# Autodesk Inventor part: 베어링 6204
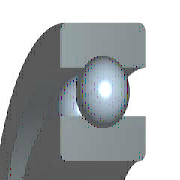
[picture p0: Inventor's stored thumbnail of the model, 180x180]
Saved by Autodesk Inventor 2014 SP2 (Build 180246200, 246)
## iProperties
IsCustomPart: 0
Created: 2009-02
Part Number: 베어링 6204
Material: 강, 연강
Description: 깊은 그루브 볼 베어링
Document SubType Name: Modeling
Standard: KS B 2023
Designer: KYOUNG IL JANG
Standards Organization: KS
Language: ko-KR
Size Designation: 6204 - 20 x 47 x 14
Categories: <MemberInstance><Categories><Category DisplayName="샤프트 부품" InternalName="7f7aeb1f-a693-4053-b835-cee3144e0d98" Mnemonic="SHFT"><Category DisplayName="베어링" Inter
Density: 7.86 g/cm^3
Mass: 104.255 g
Surface Area: 87.8912 cm^2
Volume: 13.264 cm^3
Appearance: 강철
Author: KYOUNG IL JANG
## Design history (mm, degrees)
sketch "스케치" dims "d0" = 7.02 (= -0.26 x WD + 0.26 x BD)
  geometry: L1 (3.49, 16.75)-(10.51, 16.75); L2 (7, 16.75)-(7, 13.24); L3 (7, 16.75)-(7, 20.26); L4 (4.392, 14.401)-(0, 14.401); L5 (0, 10)-(14, 10); L6 (4.392, 19.099)-(0, 19.099); L7 (0, 23.5)-(14, 23.5); L8 (14, 10)-(14, 14.401); L9 (9.608, 14.401)-(14, 14.401); L10 (9.608, 19.099)-(14, 19.099); L11 (14, 23.5)-(14, 19.099); L12 (-1.4, 0)-(8.4, 0) reference; L13 (0, -0.3)-(0, 5.3) reference
  constraints: 22 end point, 4 point on line, 2 collinear, 2 perpendicular, 2 symmetric about line, 1 midpoint, 1 parallel, 14 other
  dimensions: "d9" = 20 diameter of L5 L12 (= WD); "d11" = 47 diameter of L7 L12 (= BD); "d12" = 14 distance between parallel lines of L8 L13 (= KB); "d13" = 28.802 diameter of L9 L12 (= 0.326 x BD + 0.674 x WD)
revolve "본체" stored, may be unused: angle "d6" = 90 deg
revolve "볼" stored, may be unused: angle "d7" = 90 deg
pattern_circular "IDS_ARRAYBALL[SIMPL:T]" dims angle "d3" = 360 deg
body "Solid1"
fillet "모깎기1" dims "d1" = 1 (= KRS)
other parameters: "WD" = 20 [user parameter; used in 5 equation terms], "BD" = 47 [user parameter; used in 5 equation terms], "KB" = 14 [user parameter; used in 1 equation term], "KRS" = 1 [user parameter; used in 1 equation term], "d4" = 0, "d5" = 0, "d8" = 0, "d14" = 0, "d15" = 0, "BBA" = 0 [user parameter], "BC0" = 6550000 [user parameter], "BC" = 1.27e+07 [user parameter], "BR" = 23.5 (= 0.5 x BD) [user parameter]
